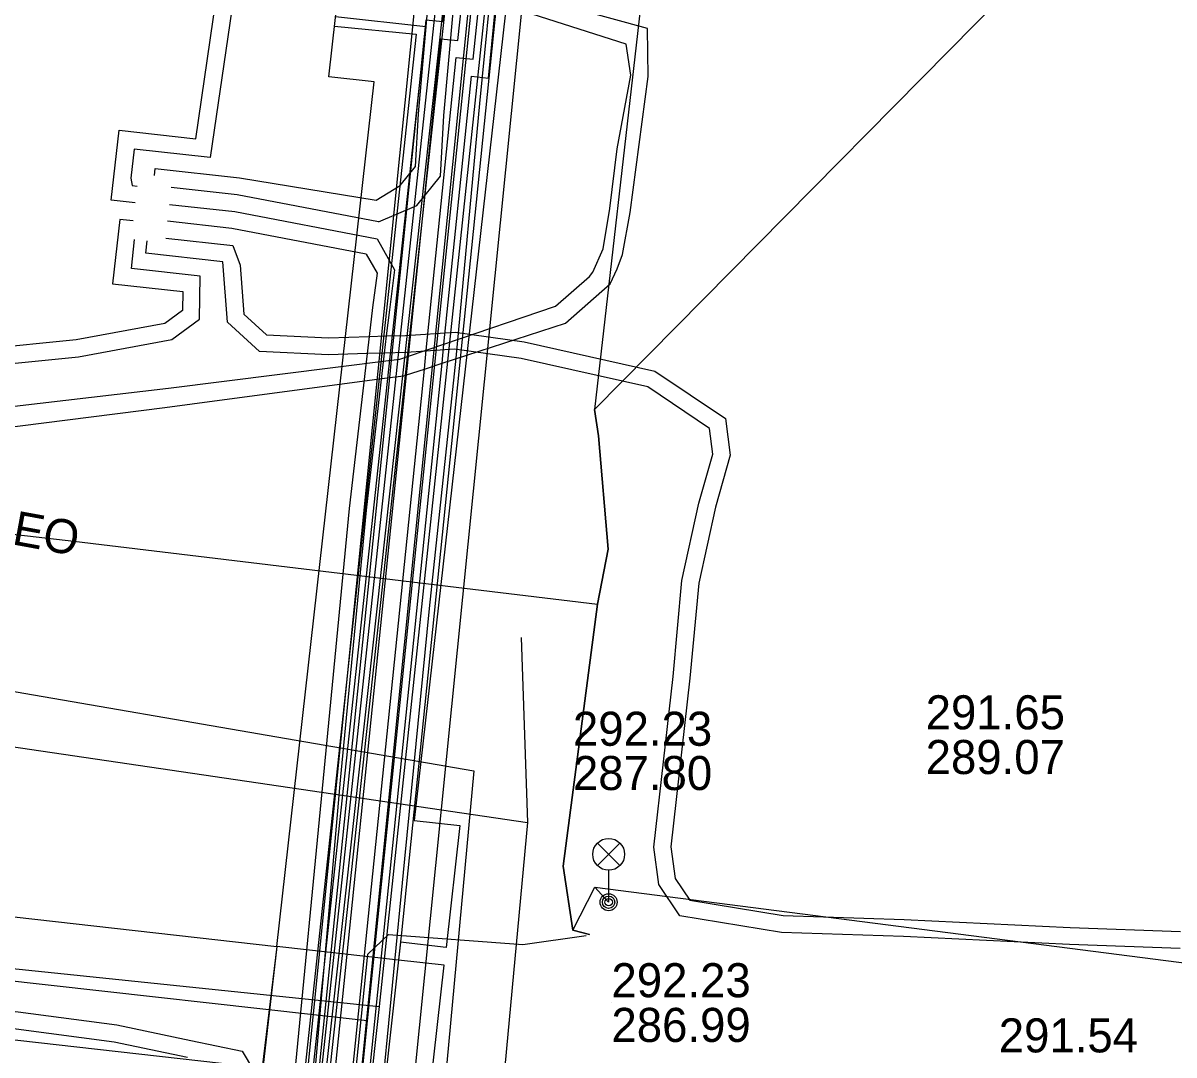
# Model space of a CAD drawing. Extents: x -595540 to -593988, y -1160850 to -1159202.
# Drawn here: x -594290.61 to -594263.57, y -1160141.08 to -1160116.83 of the extents above; entities that cross this region are included whole.
import ezdxf

# ---------------------------------------------------------------- set-up
doc = ezdxf.new("R2010")
doc.units = 0
for name, color, linetype in [('BVK-DESTOVA_popisy', 7, 'Continuous'), ('BVK-DESTOVA_trasa sítě', 7, 'Continuous'), ('BVK-SPLASKOVA_popisy', 7, 'Continuous'), ('BVK-SPLASKOVA_trasa sítě', 7, 'Continuous'), ('BVK-VODOVOD_trasa sítě', 7, 'Continuous'), ('BVK-VODOVOD_trasa zrušené sítě', 7, 'Continuous'), ('CETIN_kabel podzemní', 7, 'Continuous'), ('DESTOVA-NEPROVOZOVANA_popisy', 7, 'Continuous'), ('DESTOVA_trasa neprovozované sítě', 7, 'Continuous'), ('DSP-NN-TEPLARNY_kabel', 7, 'Continuous'), ('EON-NN_kabel', 7, 'Continuous'), ('EON-VN_kabel', 7, 'Continuous'), ('PODA_kabel optický', 7, 'Continuous'), ('TEPLARNY-ELEKTRO_kabel', 7, 'Continuous'), ('TEPLARNY-HORKOVODY_trasa sítě', 7, 'Continuous'), ('TEPLARNY-HORKOVODY_trasa sítě obvodem', 7, 'Continuous'), ('TEPLARNY-TEPLOVODY_trasa sítě', 7, 'Continuous'), ('TSB_kabel VO', 7, 'Continuous'), ('TSB_kolektor', 7, 'Continuous'), ('TSB_lampy VO', 7, 'Continuous')]:
    doc.layers.add(name, color=color, linetype=linetype)

msp = doc.modelspace()

# ---------------------------------------------------------------- linework, layer by layer
at = {"layer": 'BVK-DESTOVA_popisy'}
msp.add_line((-594276.789, -1160139.846), (-594276.789, -1160139.846), dxfattribs=at)
at = {"layer": 'BVK-DESTOVA_trasa sítě'}
msp.add_line((-594278.762, -1160135.615), (-594282.157, -1160171.949), dxfattribs=at)
msp.add_lwpolyline([(-594313.593, -1160130.477), (-594296.768, -1160132.961), (-594296.353, -1160133.022), (-594295.897, -1160133.09), (-594295.52, -1160133.145), (-594278.762, -1160135.615)], dxfattribs=at)
at = {"layer": 'BVK-SPLASKOVA_popisy'}
msp.add_line((-594277.694, -1160133.013), (-594277.694, -1160133.013), dxfattribs=at)
at = {"layer": 'BVK-SPLASKOVA_trasa sítě'}
msp.add_line((-594280.025, -1160134.4), (-594283.295, -1160169.861), dxfattribs=at)
msp.add_lwpolyline([(-594314.806, -1160128.393), (-594295.637, -1160131.704), (-594280.025, -1160134.4)], dxfattribs=at)
at = {"layer": 'BVK-VODOVOD_trasa sítě'}
msp.add_lwpolyline([(-594282.22, -1160142.42), (-594281.64, -1160136.47), (-594281.06, -1160130.59), (-594280.44, -1160124.71), (-594279.88, -1160118.72), (-594279.29, -1160112.76), (-594278.57, -1160105.82), (-594278.39, -1160104.04), (-594277.88, -1160098.86), (-594277.29, -1160092.93), (-594276.71, -1160087.03), (-594276.48, -1160084.72), (-594276.06, -1160080.86), (-594275.48, -1160074.89), (-594274.87, -1160068.94), (-594274.29, -1160062.99), (-594273.67, -1160057.03), (-594273.07, -1160051.07), (-594272.46, -1160045.11), (-594272.13, -1160041.43), (-594271.919, -1160038.964), (-594271.913, -1160038.899), (-594271.33, -1160032.21), (-594271.304, -1160031.85)], dxfattribs=at)
at = {"layer": 'BVK-VODOVOD_trasa zrušené sítě'}
msp.add_lwpolyline([(-594271.13, -1160032.71), (-594271.69, -1160038.88), (-594276.29, -1160084.04), (-594278.46, -1160106.32), (-594281.72, -1160138.21), (-594288.88, -1160202.87), (-594288.96, -1160203.44)], dxfattribs=at)
at = {"layer": 'CETIN_kabel podzemní'}
for points in [[(-594279.13, -1160110.5), (-594282.25, -1160139.94)], [(-594346.16, -1160132.67), (-594346.45, -1160133.28), (-594282.25, -1160139.94)], [(-594282.25, -1160139.94), (-594288.66, -1160197.87)]]:
    msp.add_lwpolyline(points, dxfattribs=at)
at = {"layer": 'DESTOVA-NEPROVOZOVANA_popisy'}
msp.add_line((-594269.407, -1160134.477), (-594269.407, -1160134.477), dxfattribs=at)
at = {"layer": 'DESTOVA_trasa neprovozované sítě'}
msp.add_line((-594278.907, -1160131.272), (-594278.762, -1160135.615), dxfattribs=at)
at = {"layer": 'DSP-NN-TEPLARNY_kabel'}
for points in [[(-594295.97, -1160255.318), (-594286.648, -1160169.484), (-594290.437, -1160169.027), (-594290.959, -1160168.976), (-594290.709, -1160166.783), (-594286.412, -1160167.291), (-594284.468, -1160149.424), (-594288.669, -1160148.902), (-594288.375, -1160146.818), (-594284.229, -1160147.32), (-594280.951, -1160116.816), (-594276.305, -1160074.237), (-594281.042, -1160073.871), (-594280.819, -1160071.543), (-594276.058, -1160072.001), (-594271.567, -1160030.512), (-594272.066, -1160030.463), (-594277.368, -1160029.953), (-594274.898, -1160009.552), (-594276.23, -1160009.387), (-594274.991, -1159999.506)], [(-594087.141, -1160131.465), (-594081.616, -1160132.079), (-594077.929, -1160098.007), (-594081.33, -1160097.638), (-594080.888, -1160093.562), (-594077.489, -1160093.931), (-594072.903, -1160051.451), (-594151.248, -1160042.664), (-594271.375, -1160030.557), (-594276.36, -1160076.505), (-594284.074, -1160147.539), (-594288.22, -1160147.049), (-594288.448, -1160148.755), (-594284.262, -1160149.285), (-594286.229, -1160167.438), (-594290.518, -1160166.974), (-594290.731, -1160168.788), (-594290.275, -1160168.836), (-594286.414, -1160169.302), (-594296.128, -1160258.71), (-594301.846, -1160311.412), (-594308.146, -1160310.714)], [(-594308.102, -1160310.316), (-594302.2, -1160310.97), (-594296.42, -1160257.61), (-594301.107, -1160257.121), (-594300.849, -1160254.61), (-594296.124, -1160255.112), (-594286.876, -1160169.653), (-594290.577, -1160169.211), (-594291.18, -1160169.153), (-594290.893, -1160166.577), (-594286.596, -1160167.077), (-594284.703, -1160149.572), (-594288.889, -1160149.056), (-594288.555, -1160146.56), (-594284.409, -1160147.062), (-594281.146, -1160116.918), (-594283.275, -1160116.69)], [(-594283.299, -1160116.908), (-594281.375, -1160117.093), (-594284.576, -1160146.882), (-594288.696, -1160146.38), (-594289.075, -1160149.238), (-594284.916, -1160149.741), (-594286.773, -1160166.893), (-594291.07, -1160166.385), (-594291.409, -1160169.327), (-594290.658, -1160169.403), (-594287.075, -1160169.815), (-594296.304, -1160254.906), (-594301.03, -1160254.391), (-594301.354, -1160257.297), (-594296.626, -1160257.778), (-594302.378, -1160310.749), (-594308.08, -1160310.118)]]:
    msp.add_lwpolyline(points, dxfattribs=at)
at = {"layer": 'EON-NN_kabel'}
for points in [[(-594282.317, -1160120.996), (-594281.753, -1160120.649), (-594281.394, -1160120.201), (-594281.324, -1160118.964), (-594280.982, -1160115.128), (-594280.318, -1160107.719), (-594279.388, -1160098.091), (-594278.442, -1160090.338), (-594277.59, -1160083.177), (-594276.016, -1160070.085), (-594274.711, -1160060.235), (-594273.592, -1160050.518), (-594272.9, -1160044.217), (-594272.152, -1160043.386)], [(-594282.263, -1160121.501), (-594281.359, -1160121.117), (-594280.806, -1160120.427), (-594280.726, -1160119.008), (-594280.384, -1160115.182), (-594279.72, -1160107.775), (-594278.792, -1160098.157), (-594277.846, -1160090.41), (-594276.994, -1160083.249), (-594275.42, -1160070.161), (-594274.115, -1160060.309), (-594272.996, -1160050.586), (-594272.33, -1160044.595), (-594271.712, -1160043.908)], [(-594290.977, -1160105.512), (-594290.659, -1160104.769), (-594290.166, -1160104.621), (-594288.047, -1160104.602), (-594286.186, -1160104.678), (-594284.761, -1160104.952), (-594284.335, -1160105.403), (-594284.701, -1160109.05), (-594285.341, -1160113.99), (-594286.213, -1160119.992), (-594288.001, -1160119.793), (-594288.077, -1160120.475), (-594288.053, -1160120.652), (-594287.931, -1160120.669)], [(-594287.975, -1160121.06), (-594288.543, -1160120.996), (-594288.354, -1160119.35), (-594286.553, -1160119.551), (-594285.737, -1160113.936), (-594285.099, -1160109.004), (-594284.751, -1160105.545), (-594284.963, -1160105.32), (-594286.232, -1160105.076), (-594288.053, -1160105.002), (-594290.106, -1160105.021), (-594290.365, -1160105.099), (-594290.562, -1160105.56)], [(-594288.022, -1160121.48), (-594288.34, -1160121.445), (-594288.508, -1160122.956), (-594286.859, -1160123.139), (-594286.866, -1160123.586), (-594287.284, -1160123.894), (-594289.368, -1160124.279), (-594291.556, -1160124.495), (-594294.129, -1160124.773), (-594298.947, -1160124.321), (-594301.454, -1160124.1), (-594301.697, -1160123.851), (-594302.303, -1160121.437), (-594302.43, -1160121.16), (-594303.135, -1160120.095), (-594304.837, -1160119.28), (-594307.994, -1160118.68), (-594310.903, -1160118.146)], [(-594310.971, -1160118.54), (-594308.068, -1160119.074), (-594304.963, -1160119.664), (-594303.407, -1160120.409), (-594302.78, -1160121.356), (-594302.681, -1160121.571), (-594302.059, -1160124.053), (-594301.636, -1160124.486), (-594298.983, -1160124.719), (-594294.127, -1160125.175), (-594291.514, -1160124.893), (-594289.312, -1160124.675), (-594287.12, -1160124.27), (-594286.47, -1160123.79), (-594286.454, -1160122.783), (-594288.068, -1160122.603), (-594287.992, -1160121.92)], [(-594287.524, -1160120.412), (-594287.506, -1160120.25), (-594285.525, -1160120.47), (-594282.317, -1160120.996)], [(-594282.263, -1160121.501), (-594285.581, -1160120.867), (-594287.129, -1160120.695)], [(-594287.174, -1160121.093), (-594285.64, -1160121.263), (-594282.295, -1160121.901)], [(-594282.552, -1160122.26), (-594285.709, -1160121.658), (-594287.218, -1160121.49)], [(-594282.295, -1160121.901), (-594281.883, -1160122.63), (-594282.006, -1160123.567), (-594282.078, -1160124.184), (-594282.125, -1160124.586), (-594282.554, -1160128.279), (-594283.161, -1160134.618), (-594283.763, -1160141.549), (-594283.556, -1160142.44), (-594283.685, -1160143.387), (-594283.764, -1160144.438), (-594284.219, -1160148.423), (-594284.445, -1160150.983), (-594285.251, -1160151.843), (-594287.376, -1160152.635), (-594289.888, -1160152.348)], [(-594263.429, -1160138.573), (-594266.025, -1160138.479), (-594269.927, -1160138.292), (-594272.796, -1160138.197), (-594275.186, -1160137.805), (-594275.673, -1160137.074), (-594275.796, -1160136.196), (-594275.342, -1160132.187), (-594275.134, -1160129.933), (-594274.736, -1160128.11), (-594274.408, -1160126.959), (-594274.485, -1160126.356), (-594275.931, -1160125.382), (-594278.912, -1160124.715), (-594280.476, -1160124.496), (-594281.605, -1160124.57), (-594282.125, -1160124.586), (-594282.528, -1160124.598), (-594283.44, -1160124.626), (-594285.061, -1160124.547), (-594285.81, -1160123.863), (-594285.921, -1160122.439), (-594287.727, -1160122.238), (-594287.695, -1160121.953)], [(-594287.262, -1160121.888), (-594285.684, -1160122.063), (-594285.514, -1160122.523), (-594285.424, -1160123.675), (-594284.897, -1160124.155), (-594283.436, -1160124.226), (-594282.481, -1160124.196), (-594282.078, -1160124.184), (-594281.625, -1160124.17), (-594280.462, -1160124.094), (-594278.84, -1160124.321), (-594275.771, -1160125.008), (-594274.111, -1160126.126), (-594274, -1160126.989), (-594274.348, -1160128.208), (-594274.738, -1160129.995), (-594274.944, -1160132.227), (-594275.392, -1160136.19), (-594275.289, -1160136.928), (-594274.95, -1160137.439), (-594272.756, -1160137.799), (-594269.911, -1160137.892), (-594266.009, -1160138.079), (-594263.419, -1160138.173)], [(-594282.552, -1160122.26), (-594282.297, -1160122.71), (-594282.402, -1160123.517), (-594282.481, -1160124.196), (-594282.528, -1160124.598), (-594282.952, -1160128.237), (-594283.559, -1160134.576), (-594284.261, -1160141.776), (-594284.065, -1160142.617), (-594284.085, -1160143.367), (-594284.162, -1160144.4), (-594284.617, -1160148.383), (-594284.831, -1160150.81), (-594285.479, -1160151.501), (-594287.425, -1160152.226), (-594289.838, -1160151.95)], [(-594368.167, -1160128.425), (-594362.503, -1160129.133), (-594357.041, -1160129.868), (-594351.153, -1160130.624), (-594344.576, -1160131.304), (-594339.289, -1160131.799), (-594335.156, -1160132.33), (-594329.218, -1160133.113), (-594325.574, -1160133.579), (-594319.925, -1160134.315), (-594314.956, -1160135.014), (-594310.668, -1160135.639), (-594309.141, -1160135.843), (-594306.515, -1160136.547), (-594301.192, -1160138.01), (-594295.717, -1160139.516), (-594290.725, -1160140.063), (-594288.407, -1160140.371), (-594286.667, -1160140.735)], [(-594368.221, -1160128.821), (-594362.555, -1160129.529), (-594357.093, -1160130.264), (-594351.199, -1160131.022), (-594344.616, -1160131.702), (-594339.333, -1160132.197), (-594335.208, -1160132.726), (-594329.27, -1160133.509), (-594325.626, -1160133.975), (-594319.979, -1160134.711), (-594315.012, -1160135.41), (-594310.724, -1160136.035), (-594309.219, -1160136.237), (-594306.619, -1160136.933), (-594301.298, -1160138.396), (-594295.793, -1160139.91), (-594290.773, -1160140.461), (-594288.475, -1160140.765), (-594286.749, -1160141.127)], [(-594286.667, -1160140.735), (-594285.463, -1160140.987), (-594284.467, -1160142.657), (-594284.485, -1160143.347), (-594284.56, -1160144.362), (-594285.015, -1160148.343), (-594285.217, -1160150.638), (-594285.707, -1160151.159), (-594287.473, -1160151.819), (-594289.789, -1160151.554)]]:
    msp.add_lwpolyline(points, dxfattribs=at)
at = {"layer": 'EON-VN_kabel'}
for points in [[(-594470.133, -1160006.664), (-594325.682, -1160024.094), (-594272.754, -1160031.031), (-594272.357, -1160031.083), (-594271.96, -1160031.135), (-594271.999, -1160031.517), (-594280.672, -1160116.014), (-594280.712, -1160116.411), (-594280.753, -1160116.807), (-594281.151, -1160116.766), (-594281.965, -1160124.755), (-594282.006, -1160125.164), (-594285.392, -1160158.399), (-594285.861, -1160162.602), (-594285.908, -1160163.022), (-594297.854, -1160269.994)], [(-594297.011, -1160270.069), (-594285.141, -1160163.214), (-594285.097, -1160162.813), (-594284.589, -1160158.24), (-594281.185, -1160124.963), (-594281.14, -1160124.518), (-594280.437, -1160117.644), (-594280.038, -1160117.685), (-594279.916, -1160116.492), (-594279.875, -1160116.095), (-594271.205, -1160031.621), (-594271.602, -1160031.569), (-594271.999, -1160031.517), (-594272.396, -1160031.465), (-594272.793, -1160031.413), (-594325.737, -1160024.49), (-594470.334, -1160007.043)], [(-594301.048, -1160313.903), (-594302.341, -1160313.736), (-594302.791, -1160313.678), (-594303.215, -1160313.623), (-594297.358, -1160270.118), (-594285.535, -1160163.116), (-594285.491, -1160162.714), (-594285.035, -1160158.592), (-594281.603, -1160125.099), (-594281.558, -1160124.661), (-594280.794, -1160117.205), (-594280.396, -1160117.246), (-594280.314, -1160116.451), (-594280.274, -1160116.055), (-594271.602, -1160031.569), (-594271.563, -1160031.188), (-594270.177, -1160031.369), (-594267.067, -1160031.667), (-594267.106, -1160032.072), (-594267.246, -1160033.539)], [(-594283.146, -1160159.642), (-594284.317, -1160159.512), (-594280.77, -1160124.827), (-594280.724, -1160124.376), (-594280.08, -1160118.083), (-594279.681, -1160118.124), (-594279.518, -1160116.533), (-594279.477, -1160116.136), (-594270.812, -1160031.709), (-594267.106, -1160032.072), (-594266.707, -1160032.111), (-594183.417, -1160040.258)], [(-594312.273, -1160125.157), (-594301.785, -1160126.135), (-594292.416, -1160126.519), (-594287.278, -1160125.866), (-594286.64, -1160125.777), (-594282.006, -1160125.164), (-594281.666, -1160125.119), (-594281.603, -1160125.099), (-594281.185, -1160124.963), (-594280.77, -1160124.827), (-594277.868, -1160123.882), (-594276.823, -1160122.963), (-594276.652, -1160122.606), (-594276.526, -1160122.271), (-594276.353, -1160121.28), (-594275.928, -1160118.089), (-594275.946, -1160116.962), (-594278.601, -1160116.226)], [(-594308.711, -1160125.07), (-594301.86, -1160125.704), (-594292.634, -1160126.043), (-594287.192, -1160125.41), (-594281.965, -1160124.755), (-594281.758, -1160124.729), (-594281.558, -1160124.661), (-594281.14, -1160124.518), (-594280.724, -1160124.376), (-594278.103, -1160123.481), (-594277.308, -1160122.789), (-594277.224, -1160122.689), (-594276.987, -1160122.135), (-594276.829, -1160121.191), (-594276.652, -1160119.788), (-594276.33, -1160118.055), (-594276.442, -1160117.328), (-594278.648, -1160116.622)]]:
    msp.add_lwpolyline(points, dxfattribs=at)
at = {"layer": 'PODA_kabel optický'}
msp.add_lwpolyline([(-594276.94, -1160081.899), (-594290.463, -1160204.659)], dxfattribs=at)
at = {"layer": 'TEPLARNY-ELEKTRO_kabel'}
for points in [[(-594295.97, -1160255.318), (-594286.648, -1160169.484), (-594290.437, -1160169.027), (-594290.959, -1160168.976), (-594290.709, -1160166.783), (-594286.412, -1160167.291), (-594284.468, -1160149.424), (-594288.669, -1160148.902), (-594288.375, -1160146.818), (-594284.229, -1160147.32), (-594280.951, -1160116.816), (-594276.305, -1160074.237), (-594281.042, -1160073.871), (-594280.819, -1160071.543), (-594276.058, -1160072.001), (-594271.567, -1160030.512), (-594272.066, -1160030.463), (-594277.368, -1160029.953), (-594274.898, -1160009.552), (-594276.23, -1160009.387), (-594274.991, -1159999.506)], [(-594087.141, -1160131.465), (-594081.616, -1160132.079), (-594077.929, -1160098.007), (-594081.33, -1160097.638), (-594080.888, -1160093.562), (-594077.489, -1160093.931), (-594072.903, -1160051.451), (-594151.248, -1160042.664), (-594271.375, -1160030.557), (-594276.36, -1160076.505), (-594284.074, -1160147.539), (-594288.22, -1160147.049), (-594288.448, -1160148.755), (-594284.262, -1160149.285), (-594286.229, -1160167.438), (-594290.518, -1160166.974), (-594290.731, -1160168.788), (-594290.275, -1160168.836), (-594286.414, -1160169.302), (-594296.128, -1160258.71), (-594301.846, -1160311.412), (-594308.146, -1160310.714)], [(-594308.102, -1160310.316), (-594302.2, -1160310.97), (-594296.42, -1160257.61), (-594301.107, -1160257.121), (-594300.849, -1160254.61), (-594296.124, -1160255.112), (-594286.876, -1160169.653), (-594290.577, -1160169.211), (-594291.18, -1160169.153), (-594290.893, -1160166.577), (-594286.596, -1160167.077), (-594284.703, -1160149.572), (-594288.889, -1160149.056), (-594288.555, -1160146.56), (-594284.409, -1160147.062), (-594281.146, -1160116.918), (-594283.275, -1160116.69)], [(-594283.299, -1160116.908), (-594281.375, -1160117.093), (-594284.576, -1160146.882), (-594288.696, -1160146.38), (-594289.075, -1160149.238), (-594284.916, -1160149.741), (-594286.773, -1160166.893), (-594291.07, -1160166.385), (-594291.409, -1160169.327), (-594290.658, -1160169.403), (-594287.075, -1160169.815), (-594296.304, -1160254.906), (-594301.03, -1160254.391), (-594301.354, -1160257.297), (-594296.626, -1160257.778), (-594302.378, -1160310.749), (-594308.08, -1160310.118)]]:
    msp.add_lwpolyline(points, dxfattribs=at)
at = {"layer": 'TEPLARNY-HORKOVODY_trasa sítě'}
msp.add_lwpolyline([(-594279.505, -1160110.028), (-594282.675, -1160141.562), (-594283.208, -1160146.865)], dxfattribs=at)
at = {"layer": 'TEPLARNY-HORKOVODY_trasa sítě obvodem'}
for points in [[(-594278.262, -1160110.153), (-594281.431, -1160141.687), (-594282.092, -1160148.262)], [(-594284.324, -1160145.467), (-594283.919, -1160141.437), (-594280.874, -1160111.146)]]:
    msp.add_lwpolyline(points, dxfattribs=at)
at = {"layer": 'TEPLARNY-TEPLOVODY_trasa sítě'}
for p, q in [((-594279.65, -1160112.208), (-594282.529, -1160140.277)), ((-594282.529, -1160140.277), (-594356.856, -1160131.924))]:
    msp.add_line(p, q, dxfattribs=at)
msp.add_lwpolyline([(-594282.529, -1160140.277), (-594283.164, -1160146.569), (-594287.226, -1160146.054), (-594287.665, -1160149.934), (-594283.649, -1160150.43), (-594284.577, -1160158.541), (-594285.426, -1160165.963), (-594290.333, -1160165.443), (-594290.934, -1160170.475), (-594285.959, -1160171.018), (-594289.061, -1160198.799), (-594289.814, -1160205.551), (-594293.018, -1160205.21)], dxfattribs=at)
at = {"layer": 'TSB_kabel VO'}
for points in [[(-594270.25, -1160066.294), (-594271.55, -1160079.352), (-594272.394, -1160081.943), (-594272.507, -1160085.826), (-594274.646, -1160102.822), (-594276.115, -1160116.533), (-594275.66, -1160113.52), (-594275.873, -1160116.556), (-594276.115, -1160116.533), (-594277.19, -1160125.915), (-594277.097, -1160126.532), (-594276.867, -1160129.194), (-594277.114, -1160130.483), (-594277.927, -1160136.645), (-594277.695, -1160138.145), (-594277.302, -1160138.244)], [(-594277.302, -1160138.244), (-594277.695, -1160138.145), (-594277.927, -1160136.645), (-594277.114, -1160130.483), (-594276.867, -1160129.194), (-594277.097, -1160126.532), (-594277.19, -1160125.915), (-594265.027, -1160113.592), (-594253.459, -1160101.338), (-594253.678, -1160101.093), (-594253.459, -1160101.338), (-594252.019, -1160099.734), (-594250.656, -1160087.6), (-594249.414, -1160074.477)], [(-594318.159, -1160123.106), (-594306.514, -1160124.433), (-594303.617, -1160125.101), (-594303.5, -1160124.809), (-594303.617, -1160125.101), (-594302.12, -1160125.322), (-594302.025, -1160127.554), (-594289.418, -1160129.007), (-594277.114, -1160130.483), (-594277.927, -1160136.645), (-594277.695, -1160138.145), (-594277.302, -1160138.244)], [(-594277.302, -1160138.244), (-594277.695, -1160138.145), (-594277.18, -1160137.138), (-594276.855, -1160137.488), (-594277.18, -1160137.138), (-594262.603, -1160139.005), (-594248.779, -1160140.683), (-594248.732, -1160140.297), (-594248.779, -1160140.683), (-594248.313, -1160140.733), (-594245.384, -1160141.14), (-594233.466, -1160142.653), (-594221.829, -1160144.067), (-594221.773, -1160143.709), (-594221.829, -1160144.067), (-594215.04, -1160144.925)], [(-594282.78, -1160141.32), (-594282.51, -1160138.71), (-594282.03, -1160138.25), (-594278.87, -1160138.48), (-594277.382, -1160138.273)]]:
    msp.add_lwpolyline(points, dxfattribs=at)
at = {"layer": 'TSB_kolektor'}
for points in [[(-594278.756, -1160111.972), (-594278.804, -1160112.39), (-594277.732, -1160112.509), (-594278.052, -1160115.371), (-594279.127, -1160115.252), (-594281.421, -1160135.568), (-594280.349, -1160135.687), (-594280.67, -1160138.549), (-594281.745, -1160138.43), (-594281.792, -1160138.847), (-594284.654, -1160138.526), (-594282.36, -1160118.212), (-594283.432, -1160118.093), (-594283.111, -1160115.231), (-594282.036, -1160115.35), (-594281.616, -1160111.625)], [(-594284.977, -1160141.388), (-594312.937, -1160138.23), (-594313.035, -1160139.114), (-594315.898, -1160138.796), (-594315.87, -1160138.551), (-594316.287, -1160138.505), (-594316.678, -1160142.029), (-594322.82, -1160141.346), (-594322.43, -1160137.833), (-594322.849, -1160137.788), (-594322.874, -1160138.02), (-594325.737, -1160137.701), (-594325.636, -1160136.796), (-594357.496, -1160133.198), (-594357.173, -1160130.336), (-594356.359, -1160130.428), (-594356.239, -1160129.356), (-594353.457, -1160129.668), (-594353.577, -1160130.742), (-594284.654, -1160138.526)], [(-594284.654, -1160138.526), (-594284.998, -1160141.372), (-594282.115, -1160141.709), (-594281.04, -1160141.829), (-594280.72, -1160138.967), (-594281.792, -1160138.847)]]:
    msp.add_lwpolyline(points, close=True, dxfattribs=at)
at = {"layer": 'TSB_lampy VO'}
for p, q in [((-594277.12, -1160136.628), (-594276.59, -1160136.098)), ((-594277.12, -1160136.098), (-594276.59, -1160136.628)), ((-594277.12, -1160136.628), (-594276.59, -1160136.098)), ((-594277.12, -1160136.098), (-594276.59, -1160136.628)), ((-594276.855, -1160136.738), (-594276.855, -1160137.488)), ((-594276.855, -1160136.738), (-594276.855, -1160137.488))]:
    msp.add_line(p, q, dxfattribs=at)
for centre, radius in [((-594276.855, -1160136.363), 0.375), ((-594276.855, -1160136.363), 0.375), ((-594276.855, -1160137.488), 0.2), ((-594276.855, -1160137.488), 0.2), ((-594276.855, -1160137.488), 0.145), ((-594276.855, -1160137.488), 0.145), ((-594276.855, -1160137.488), 0.0876), ((-594276.855, -1160137.488), 0.0876)]:
    msp.add_circle(centre, radius, dxfattribs=at)

# ---------------------------------------------------------------- texts
at = {"layer": 'BVK-DESTOVA_popisy'}
for s, p in [('292.23', (-594276.789, -1160139.721)), ('286.99', (-594276.789, -1160140.771))]:
    msp.add_text(s, height=0.8, dxfattribs=at).set_placement(p)
at = {"layer": 'BVK-SPLASKOVA_popisy'}
msp.add_text('DN 300 BEO', height=0.8, rotation=349.5959, dxfattribs=at).set_placement((-594295.456, -1160128.238))
for s, p in [('292.23', (-594277.694, -1160133.813)), ('287.80', (-594277.694, -1160134.853))]:
    msp.add_text(s, height=0.8, dxfattribs=at).set_placement(p)
at = {"layer": 'DESTOVA-NEPROVOZOVANA_popisy'}
for s, p in [('291.65', (-594269.407, -1160133.427)), ('289.07', (-594269.407, -1160134.477)), ('291.54', (-594267.69, -1160141.017))]:
    msp.add_text(s, height=0.8, dxfattribs=at).set_placement(p)

doc.saveas('drawing.dxf')
